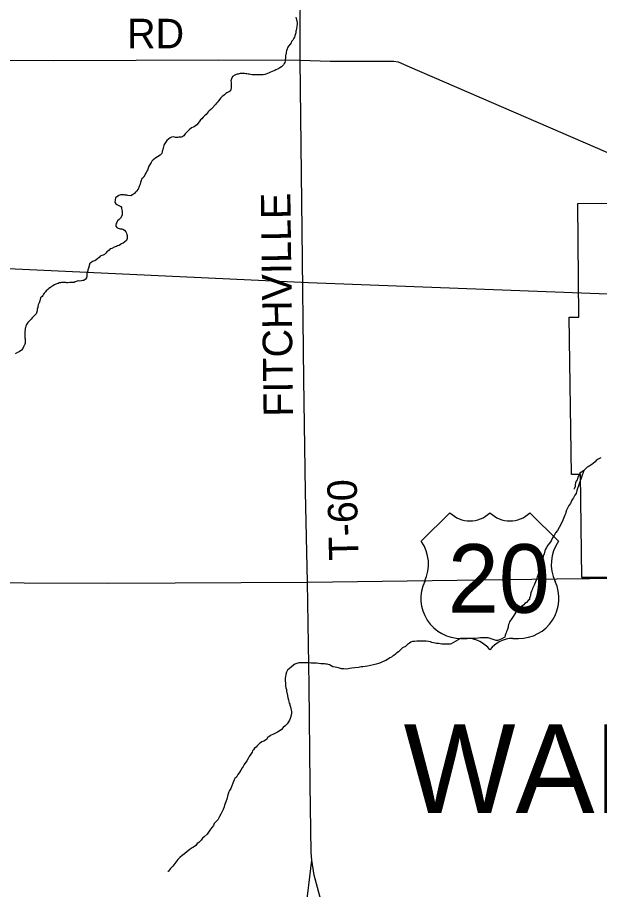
# Model space of a CAD drawing. Extents: x 0 to 34, y 0 to 22.
# Drawn here: x 3.195 to 4.314, y 17.124 to 18.8 of the extents above; entities that cross this region are included whole.
import ezdxf

# ---------------------------------------------------------------- set-up
doc = ezdxf.new("R2010")
doc.units = 0
for name, color, linetype in [('GM_X_Corporation', 7, 'Continuous'), ('GM_X_County_Road', 7, 'Continuous'), ('GM_X_Minor_River', 7, 'Continuous'), ('GM_X_Rail_Line', 7, 'Continuous'), ('GM_X_Township_Road', 7, 'Continuous'), ('GM_X_Township_Road_Text', 7, 'Continuous'), ('GM_X_Township_Text', 7, 'Continuous'), ('GM_X_US_Location', 7, 'Continuous'), ('GM_X_US_Route', 7, 'Continuous'), ('GM_X_US_Shield', 7, 'Continuous')]:
    doc.layers.add(name, color=color, linetype=linetype)

msp = doc.modelspace()

# ---------------------------------------------------------------- linework, layer by layer
at = {"layer": 'GM_X_Corporation'}
msp.add_lwpolyline([(4.3607, 17.7236), (4.2797, 17.7236), (4.2768, 17.9218), (4.2598, 17.9214), (4.2553, 18.2244), (4.274, 18.2242), (4.2721, 18.4427), (4.5184, 18.4448)], dxfattribs=at)
at = {"layer": 'GM_X_County_Road'}
msp.add_lwpolyline([(3.5195, 15.1803), (3.5207, 15.2006), (3.5211, 15.2036), (3.5293, 15.2558), (3.5414, 15.3335), (3.5433, 15.3555), (3.5444, 15.384), (3.544, 15.4372), (3.5428, 15.4611), (3.5426, 15.4998), (3.5435, 15.5143), (3.548, 15.5436), (3.572, 15.7092), (3.6074, 15.9775), (3.6369, 16.2036), (3.6567, 16.349), (3.7031, 16.7163), (3.7483, 17.0786), (3.7604, 17.1798), (3.7595, 17.1946), (3.7574, 17.3264), (3.7557, 17.5159), (3.7523, 17.7146)], dxfattribs=at)
at = {"layer": 'GM_X_Minor_River'}
for points in [[(3.7298, 18.8012), (3.7305, 18.7985), (3.7309, 18.7962), (3.7317, 18.7935), (3.7321, 18.7901), (3.7324, 18.7875), (3.732, 18.7837), (3.7313, 18.7783), (3.7305, 18.7757), (3.7301, 18.7738), (3.7298, 18.7711), (3.7294, 18.7692), (3.7286, 18.7669), (3.7282, 18.765), (3.7275, 18.7624), (3.7263, 18.7605), (3.724, 18.757), (3.7218, 18.7544), (3.7206, 18.7517), (3.7187, 18.7491), (3.716, 18.7453), (3.7145, 18.743), (3.7126, 18.738), (3.7122, 18.7361), (3.7115, 18.7339), (3.7111, 18.7304), (3.7103, 18.7278), (3.7099, 18.7221), (3.7096, 18.719), (3.7092, 18.7167), (3.7084, 18.7141), (3.7077, 18.7118), (3.7061, 18.7091), (3.7042, 18.7076), (3.7023, 18.7057), (3.6993, 18.7038), (3.6974, 18.7023), (3.6947, 18.7012), (3.6917, 18.6996), (3.6894, 18.6985), (3.6875, 18.6977), (3.6841, 18.6966), (3.681, 18.6955), (3.6784, 18.6939), (3.6757, 18.6928), (3.6723, 18.6913), (3.6704, 18.6909), (3.667, 18.6901), (3.6635, 18.6898), (3.6613, 18.6898), (3.6586, 18.6902), (3.6563, 18.6898), (3.6533, 18.6898), (3.6506, 18.6902), (3.648, 18.6902), (3.6461, 18.6902), (3.6427, 18.6906), (3.64, 18.6913), (3.6381, 18.6917), (3.6358, 18.6921), (3.6339, 18.6921), (3.6309, 18.6925), (3.6282, 18.6925), (3.6256, 18.6925), (3.6229, 18.6925), (3.6191, 18.6913), (3.6172, 18.6913), (3.6149, 18.6906), (3.6123, 18.6894), (3.6084, 18.6868), (3.6065, 18.6826), (3.6054, 18.6803), (3.605, 18.6784), (3.6054, 18.6757), (3.6058, 18.6738), (3.6058, 18.6719), (3.6058, 18.6681), (3.6054, 18.6651), (3.6046, 18.6617), (3.6042, 18.6594), (3.6023, 18.6579), (3.6001, 18.6567), (3.5974, 18.6552), (3.5955, 18.6541), (3.5925, 18.6518), (3.5902, 18.6499), (3.5883, 18.6484), (3.5852, 18.645), (3.5837, 18.6431), (3.5814, 18.64), (3.5795, 18.6374), (3.5776, 18.6358), (3.5753, 18.6328), (3.5689, 18.6263), (3.5662, 18.6237), (3.5635, 18.6206), (3.5613, 18.6191), (3.5575, 18.6138), (3.5544, 18.6115), (3.5517, 18.6085)], [(3.5517, 18.6085), (3.5491, 18.6058), (3.5468, 18.6035), (3.5438, 18.5997), (3.5419, 18.5971), (3.5396, 18.594), (3.5373, 18.5921), (3.5346, 18.5902), (3.5327, 18.5895), (3.5293, 18.5883), (3.5251, 18.5845), (3.5225, 18.5815), (3.5194, 18.5792), (3.5171, 18.5766), (3.5145, 18.5731), (3.5126, 18.5716), (3.5099, 18.5705), (3.508, 18.5701), (3.505, 18.5701), (3.5031, 18.5697), (3.5012, 18.5697), (3.4985, 18.5697), (3.4966, 18.5701), (3.494, 18.5709), (3.4909, 18.5705), (3.4882, 18.569), (3.4852, 18.5667), (3.4818, 18.564), (3.4806, 18.5621), (3.4791, 18.5602), (3.478, 18.5583), (3.4768, 18.5561), (3.4761, 18.5542), (3.4757, 18.5519), (3.4749, 18.5492), (3.4745, 18.5469), (3.4738, 18.5446), (3.473, 18.5424), (3.4723, 18.5389), (3.4692, 18.5359), (3.4639, 18.5325), (3.4608, 18.5302), (3.4574, 18.5279), (3.4555, 18.5268), (3.4529, 18.5241), (3.4517, 18.5218), (3.4506, 18.5199), (3.4483, 18.5165), (3.4475, 18.5146), (3.4468, 18.5123), (3.4456, 18.5089), (3.4445, 18.5066), (3.4433, 18.5047), (3.4422, 18.5021), (3.4411, 18.5002), (3.4395, 18.4975), (3.438, 18.4949), (3.4361, 18.4922), (3.4342, 18.4911), (3.4334, 18.4892), (3.4327, 18.4869), (3.4315, 18.4831), (3.4304, 18.48), (3.4296, 18.4774), (3.4289, 18.4751), (3.4266, 18.4705), (3.4239, 18.4663), (3.4216, 18.4644), (3.4197, 18.4622), (3.4178, 18.4606), (3.4159, 18.4591), (3.4129, 18.4576), (3.4068, 18.4584), (3.4049, 18.4588), (3.4019, 18.4588), (3.4, 18.4591), (3.3981, 18.4591), (3.3962, 18.4595), (3.3935, 18.4595), (3.3897, 18.4584), (3.3852, 18.455), (3.3833, 18.4542), (3.3825, 18.4493), (3.3821, 18.4455), (3.384, 18.442), (3.3859, 18.4409), (3.3886, 18.4394), (3.3912, 18.4382), (3.3935, 18.4371), (3.3946, 18.4348), (3.395, 18.4329), (3.3954, 18.4306), (3.3961, 18.4276), (3.3961, 18.4238), (3.3958, 18.4203), (3.3927, 18.4146), (3.3904, 18.412), (3.3874, 18.4097), (3.3859, 18.4063), (3.3847, 18.4044), (3.384, 18.4013)], [(3.384, 18.4013), (3.384, 18.3991), (3.3858, 18.3964), (3.3881, 18.3953), (3.39, 18.3949), (3.3923, 18.3941), (3.3953, 18.3937), (3.3976, 18.3933), (3.4007, 18.3914), (3.4033, 18.3884), (3.4045, 18.3857), (3.4052, 18.3831), (3.4056, 18.3812), (3.4056, 18.3781), (3.4056, 18.3751), (3.4041, 18.3717), (3.4014, 18.369), (3.398, 18.3663), (3.3949, 18.3652), (3.3927, 18.3637), (3.39, 18.3622), (3.387, 18.361), (3.3851, 18.3599), (3.3828, 18.3595), (3.3805, 18.3587), (3.3763, 18.3565), (3.3733, 18.3553), (3.371, 18.353), (3.3687, 18.3512), (3.3668, 18.3496), (3.3645, 18.347), (3.3619, 18.3447), (3.3596, 18.3436), (3.3569, 18.3428), (3.3535, 18.3413), (3.3516, 18.339), (3.3485, 18.336), (3.3459, 18.3341), (3.3432, 18.3325), (3.3409, 18.3318), (3.339, 18.331), (3.3356, 18.3284), (3.333, 18.3272), (3.333, 18.3253), (3.3314, 18.3181), (3.3303, 18.3154), (3.3299, 18.3135), (3.3284, 18.3086), (3.3284, 18.3052), (3.328, 18.3033), (3.3272, 18.2995), (3.3257, 18.2972), (3.3223, 18.2949), (3.3204, 18.2945), (3.3177, 18.2938), (3.3139, 18.2934), (3.3113, 18.2938), (3.3078, 18.293), (3.3059, 18.2919), (3.3037, 18.2911), (3.3006, 18.2907), (3.298, 18.2907), (3.2953, 18.2907), (3.2915, 18.2904), (3.2896, 18.2904), (3.2877, 18.2907), (3.2854, 18.2907), (3.2831, 18.2907), (3.2812, 18.2908), (3.2793, 18.2908), (3.2774, 18.2904), (3.2752, 18.29), (3.2729, 18.2892), (3.2706, 18.2885), (3.2683, 18.2877), (3.2657, 18.2862), (3.263, 18.2847), (3.2603, 18.2832), (3.2584, 18.2813), (3.2554, 18.2794), (3.2531, 18.2775), (3.2501, 18.2748), (3.2485, 18.2729), (3.2463, 18.2702), (3.2451, 18.2683), (3.2436, 18.2661), (3.2421, 18.2642), (3.2394, 18.2611), (3.2379, 18.2558), (3.2364, 18.252), (3.2348, 18.2478), (3.2341, 18.2448), (3.2337, 18.2429), (3.2329, 18.2395), (3.2325, 18.2364), (3.2322, 18.2345), (3.231, 18.2307), (3.2291, 18.2284), (3.2272, 18.2265), (3.2249, 18.2246), (3.223, 18.2227)], [(3.223, 18.2227), (3.2211, 18.2204), (3.2192, 18.2182), (3.2166, 18.2159), (3.215, 18.214), (3.2124, 18.2098), (3.2112, 18.2071), (3.2105, 18.2041), (3.2097, 18.2022), (3.2093, 18.1999), (3.2089, 18.1969), (3.2089, 18.1946), (3.2089, 18.1927), (3.2089, 18.19), (3.2089, 18.1874), (3.2089, 18.1847), (3.2093, 18.1828), (3.2093, 18.1798), (3.2093, 18.1767), (3.2093, 18.1741), (3.2089, 18.1722), (3.2078, 18.1699), (3.2066, 18.1672), (3.2051, 18.1638), (3.2024, 18.1607), (3.2005, 18.1596), (3.1979, 18.1577), (3.1948, 18.1562), (3.1907, 18.1535)], [(4.3163, 17.9537), (4.3133, 17.9522), (4.311, 17.951), (4.3091, 17.9499), (4.3068, 17.9484), (4.3049, 17.9457), (4.3019, 17.9431), (4.2988, 17.9408), (4.2969, 17.9393), (4.2939, 17.9377), (4.292, 17.9366), (4.2901, 17.9355), (4.2882, 17.9343), (4.2866, 17.9324), (4.2836, 17.9294)], [(4.2836, 17.9294), (4.2701, 17.8909), (4.2685, 17.8852), (4.2662, 17.8822), (4.2647, 17.8792), (4.2635, 17.8766), (4.2619, 17.8739), (4.26, 17.8709), (4.258, 17.866), (4.2546, 17.8622), (4.253, 17.8592), (4.2518, 17.8566), (4.2503, 17.8532), (4.2491, 17.8494), (4.2479, 17.846), (4.2471, 17.8433), (4.2432, 17.8335), (4.2405, 17.8282), (4.2362, 17.8199), (4.2327, 17.8142), (4.2292, 17.8093), (4.2261, 17.8044), (4.2234, 17.7999), (4.2203, 17.7942), (4.2172, 17.7897), (4.2145, 17.7855), (4.2118, 17.7814), (4.2098, 17.778), (4.2083, 17.775), (4.2071, 17.7693), (4.2055, 17.7647), (4.2043, 17.7598), (4.2027, 17.7537), (4.2015, 17.7481), (4.1999, 17.7431), (4.1983, 17.7378), (4.1964, 17.7318), (4.1948, 17.7272), (4.194, 17.7246), (4.1924, 17.7197), (4.1905, 17.7151), (4.1889, 17.7121), (4.1877, 17.7087), (4.1862, 17.7053), (4.185, 17.7026), (4.1838, 17.7), (4.183, 17.697), (4.1818, 17.6939), (4.181, 17.6909), (4.1806, 17.6882), (4.1798, 17.6856), (4.1791, 17.6837), (4.1787, 17.6814), (4.1767, 17.6795), (4.1733, 17.6754), (4.1702, 17.6735), (4.1679, 17.6709), (4.1637, 17.6679), (4.161, 17.6668), (4.1594, 17.6642), (4.156, 17.6596), (4.1525, 17.6566), (4.1509, 17.6536), (4.1478, 17.6483), (4.1451, 17.6449), (4.1405, 17.6382), (4.1401, 17.6359), (4.1389, 17.6329), (4.1381, 17.6302), (4.1377, 17.6279), (4.1369, 17.6245), (4.1361, 17.6222), (4.135, 17.6196), (4.1338, 17.617), (4.133, 17.6143), (4.1322, 17.6124), (4.1314, 17.6086), (4.1245, 17.6049), (4.1176, 17.6027), (4.1146, 17.6024), (4.1112, 17.6039), (4.1055, 17.6059), (4.0995, 17.6075), (4.0953, 17.6075), (4.0922, 17.6076), (4.0888, 17.6076), (4.085, 17.6073), (4.0801, 17.6069), (4.0743, 17.6063), (4.0683, 17.6063), (4.0622, 17.606), (4.0542, 17.6061), (4.0493, 17.6062), (4.0466, 17.6062), (4.0282, 17.5958), (4.0263, 17.5954), (4.0233, 17.5951), (4.0202, 17.5951), (4.0161, 17.5952), (4.0104, 17.5956), (4.0043, 17.5964)], [(4.2836, 17.9294), (4.2809, 17.9279), (4.2787, 17.926), (4.2756, 17.9244), (4.2733, 17.9184), (4.2718, 17.9165), (4.2703, 17.9111), (4.2688, 17.9088), (4.2676, 17.9058), (4.2669, 17.902), (4.2665, 17.8986), (4.2657, 17.8955), (4.2649, 17.895), (4.2649, 17.895), (4.2649, 17.8933)], [(4.0043, 17.5964), (4.0001, 17.5969), (3.9975, 17.5973), (3.9944, 17.5981), (3.9914, 17.5989), (3.9884, 17.5997), (3.9849, 17.6005), (3.9804, 17.6009), (3.9773, 17.6009), (3.9743, 17.601), (3.9709, 17.601), (3.9667, 17.6011), (3.9621, 17.6011), (3.958, 17.6008), (3.9542, 17.6005), (3.9511, 17.5994), (3.948, 17.5975), (3.9446, 17.5949), (3.9404, 17.5907), (3.935, 17.5881), (3.9327, 17.5863), (3.9296, 17.5833), (3.9269, 17.5806), (3.9239, 17.5784), (3.9212, 17.5761), (3.9181, 17.5739), (3.9154, 17.572), (3.9135, 17.5705), (3.9108, 17.569), (3.9078, 17.5672), (3.9028, 17.5642), (3.8978, 17.562), (3.8928, 17.5597), (3.8886, 17.5583), (3.8844, 17.5568), (3.8791, 17.5557), (3.8734, 17.5543), (3.8677, 17.5532), (3.8631, 17.5525), (3.8589, 17.5518), (3.8555, 17.5518), (3.8502, 17.5508), (3.8433, 17.5497), (3.8372, 17.549), (3.833, 17.5483), (3.8281, 17.5476), (3.8224, 17.5477), (3.8174, 17.5481), (3.8118, 17.5497), (3.8053, 17.5513), (3.8008, 17.5521), (3.7977, 17.5537), (3.7943, 17.5556), (3.7902, 17.5568), (3.7875, 17.5572), (3.7852, 17.5576), (3.783, 17.5576), (3.7811, 17.5577), (3.7776, 17.5577), (3.7738, 17.5581), (3.7697, 17.5586), (3.7643, 17.559), (3.7594, 17.5591), (3.7541, 17.5595), (3.7488, 17.5596), (3.7446, 17.5596), (3.7404, 17.5597), (3.7358, 17.5593), (3.7316, 17.5582), (3.7278, 17.5571), (3.7255, 17.5549), (3.7213, 17.5515), (3.7171, 17.5481), (3.714, 17.5455), (3.7121, 17.5414), (3.7105, 17.5368), (3.7101, 17.533), (3.7096, 17.53), (3.7096, 17.5277), (3.7096, 17.5239), (3.7099, 17.522), (3.7099, 17.5193), (3.7102, 17.5152), (3.7109, 17.5114), (3.7117, 17.5083), (3.712, 17.5053), (3.7138, 17.4969), (3.7145, 17.4923), (3.7156, 17.4881), (3.7163, 17.4847), (3.717, 17.482), (3.7182, 17.4801), (3.7185, 17.4782), (3.7196, 17.4751), (3.7203, 17.4717), (3.7211, 17.4687), (3.7214, 17.466), (3.7214, 17.463), (3.7205, 17.4561), (3.719, 17.4523), (3.7174, 17.4493)], [(3.7174, 17.4493), (3.7155, 17.4463), (3.7131, 17.4421), (3.7093, 17.4384), (3.7058, 17.4354), (3.7016, 17.4309), (3.6947, 17.426), (3.6855, 17.4219), (3.6825, 17.4205), (3.6806, 17.4193), (3.6779, 17.4175), (3.676, 17.4164), (3.6732, 17.4122), (3.6686, 17.4088), (3.6648, 17.4074), (3.6621, 17.4055), (3.6598, 17.4044), (3.6579, 17.4025), (3.6556, 17.4002), (3.6533, 17.3976), (3.6506, 17.3954), (3.6487, 17.3923), (3.6468, 17.3905), (3.6456, 17.3874), (3.6433, 17.384), (3.6402, 17.3791), (3.6382, 17.3754), (3.6355, 17.3712), (3.6308, 17.3637), (3.6289, 17.3603), (3.627, 17.3573), (3.6243, 17.3531), (3.6212, 17.3482), (3.6181, 17.3448), (3.6157, 17.3399), (3.6127, 17.3369), (3.6111, 17.3346), (3.6087, 17.3278), (3.6068, 17.3229), (3.6048, 17.3176), (3.6025, 17.3138), (3.6013, 17.3116), (3.5994, 17.3055), (3.597, 17.2972), (3.5942, 17.2892), (3.593, 17.2858), (3.5919, 17.2824), (3.5903, 17.2775), (3.5879, 17.2722), (3.5856, 17.2688), (3.5829, 17.2639), (3.5798, 17.2575), (3.5755, 17.2529), (3.5732, 17.2503), (3.5713, 17.2469), (3.5686, 17.2428), (3.5647, 17.2375), (3.5593, 17.2303), (3.5539, 17.2251), (3.5505, 17.2225), (3.5477, 17.2183), (3.5435, 17.2142), (3.5405, 17.2123), (3.5374, 17.2085), (3.5331, 17.2052), (3.5293, 17.2033), (3.5259, 17.2003), (3.5213, 17.1966), (3.5159, 17.1925), (3.5113, 17.1891), (3.5071, 17.1853), (3.5028, 17.1812), (3.4932, 17.1684), (3.4889, 17.1643), (3.487, 17.1616), (3.4854, 17.1586), (3.4843, 17.1582), (3.4839, 17.1582)]]:
    msp.add_lwpolyline(points, dxfattribs=at)
at = {"layer": 'GM_X_Rail_Line'}
msp.add_lwpolyline([(2.1, 18.3652), (2.4476, 18.3515), (3.7542, 18.2908), (4.7355, 18.2536), (4.912, 18.2502), (5.0326, 18.2535), (5.2097, 18.2563), (5.4881, 18.3005), (6.2957, 18.4383), (6.9068, 18.5576), (7.5368, 18.6745), (7.9374, 18.7476)], dxfattribs=at)
at = {"layer": 'GM_X_Township_Road'}
for points in [[(3.738, 18.7184), (3.7385, 18.9099), (3.7354, 19.1854), (3.7335, 19.3549), (3.7336, 19.3705), (3.7359, 19.383), (3.7506, 19.4392), (3.7871, 19.5729), (3.7972, 19.6165), (3.8045, 19.6522), (3.8112, 19.694), (3.817, 19.7314)], [(2.7026, 18.7182), (2.939, 18.7191), (3.2644, 18.7179), (3.5814, 18.719), (3.738, 18.7184), (3.796, 18.7166), (3.8897, 18.7163), (3.9185, 18.7162), (3.9265, 18.7154), (3.9481, 18.7058), (4.4619, 18.4832), (4.4984, 18.4668), (4.5115, 18.459), (4.5164, 18.4527)], [(3.7523, 17.7146), (3.7484, 17.888), (3.7453, 18.1043), (3.7423, 18.3916), (3.738, 18.7184)], [(4.0826, 15.9928), (4.0662, 16.0363), (4.0166, 16.2071), (3.9886, 16.3154), (3.9558, 16.4385), (3.9249, 16.5538), (3.8676, 16.7702), (3.802, 17.0136), (3.7651, 17.1512), (3.7604, 17.1798)]]:
    msp.add_lwpolyline(points, dxfattribs=at)
at = {"layer": 'GM_X_US_Route'}
for points in [[(4.2949, 17.7218), (4.3333, 17.7221), (4.3623, 17.7229), (4.3841, 17.7256), (4.3856, 17.7259)], [(2.7186, 17.715), (3.3704, 17.7126), (3.7523, 17.7146), (4.2798, 17.7216), (4.2949, 17.7218)]]:
    msp.add_lwpolyline(points, dxfattribs=at)
at = {"layer": 'GM_X_US_Shield'}
for p, q in [((4.026, 17.8481), (3.971, 17.7932)), ((4.2347, 17.7932), (4.1798, 17.8481)), ((4.0479, 17.6064), (4.0589, 17.6064)), ((4.1468, 17.6064), (4.1578, 17.6064))]:
    msp.add_line(p, q, dxfattribs=at)
for centre, radius, start, end in [((4.0644, 17.8873), 0.0549, 225.573, 314.427), ((4.1413, 17.8873), 0.0549, 225.573, 314.427), ((3.908, 17.7491), 0.0769, 334.5471, 35.0009), ((4.2977, 17.7491), 0.0769, 144.9991, 205.4529), ((4.0471, 17.6833), 0.0769, 154.8319, 270.6383), ((4.1587, 17.6833), 0.0769, 269.3617, 25.1681), ((4.0589, 17.5515), 0.0549, 36.8699, 90), ((4.1468, 17.5515), 0.0549, 90, 143.1301)]:
    msp.add_arc(centre, radius, start, end, dxfattribs=at)

# ---------------------------------------------------------------- texts
at = {"layer": 'GM_X_Township_Road_Text'}
for s, rotation, p in [('RD', 0, (3.4054, 18.7411)), ('FITCHVILLE', 90.7148, (3.7247, 18.033)), ('T-60', 91.4072, (3.8506, 17.757))]:
    msp.add_text(s, height=0.05682, rotation=rotation, dxfattribs=at).set_placement(p)
at = {"layer": 'GM_X_Township_Text'}
msp.add_text('WAKEMAN', height=0.17045, rotation=0, dxfattribs=at).set_placement((3.937, 17.2708))
at = {"layer": 'GM_X_US_Location'}
for s in ['0', '/']:
    msp.add_text(s, height=0.000189, dxfattribs=at).set_placement((4.1028, 17.7207))
msp.add_text('20', height=0.000189, rotation=0, dxfattribs=at).set_placement((4.0637, 17.6815))
at = {"layer": 'GM_X_US_Shield'}
msp.add_text('20', height=0.13184, dxfattribs=at).set_placement((4.022, 17.6558))

doc.saveas('drawing.dxf')
